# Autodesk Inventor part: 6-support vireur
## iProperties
Created: 2011-02
Part Number: 6-support vireur
Document SubType Name: Modeling
Designer: eric
Density: 1 g/cm^3
Author: eric
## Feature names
1. Base1
